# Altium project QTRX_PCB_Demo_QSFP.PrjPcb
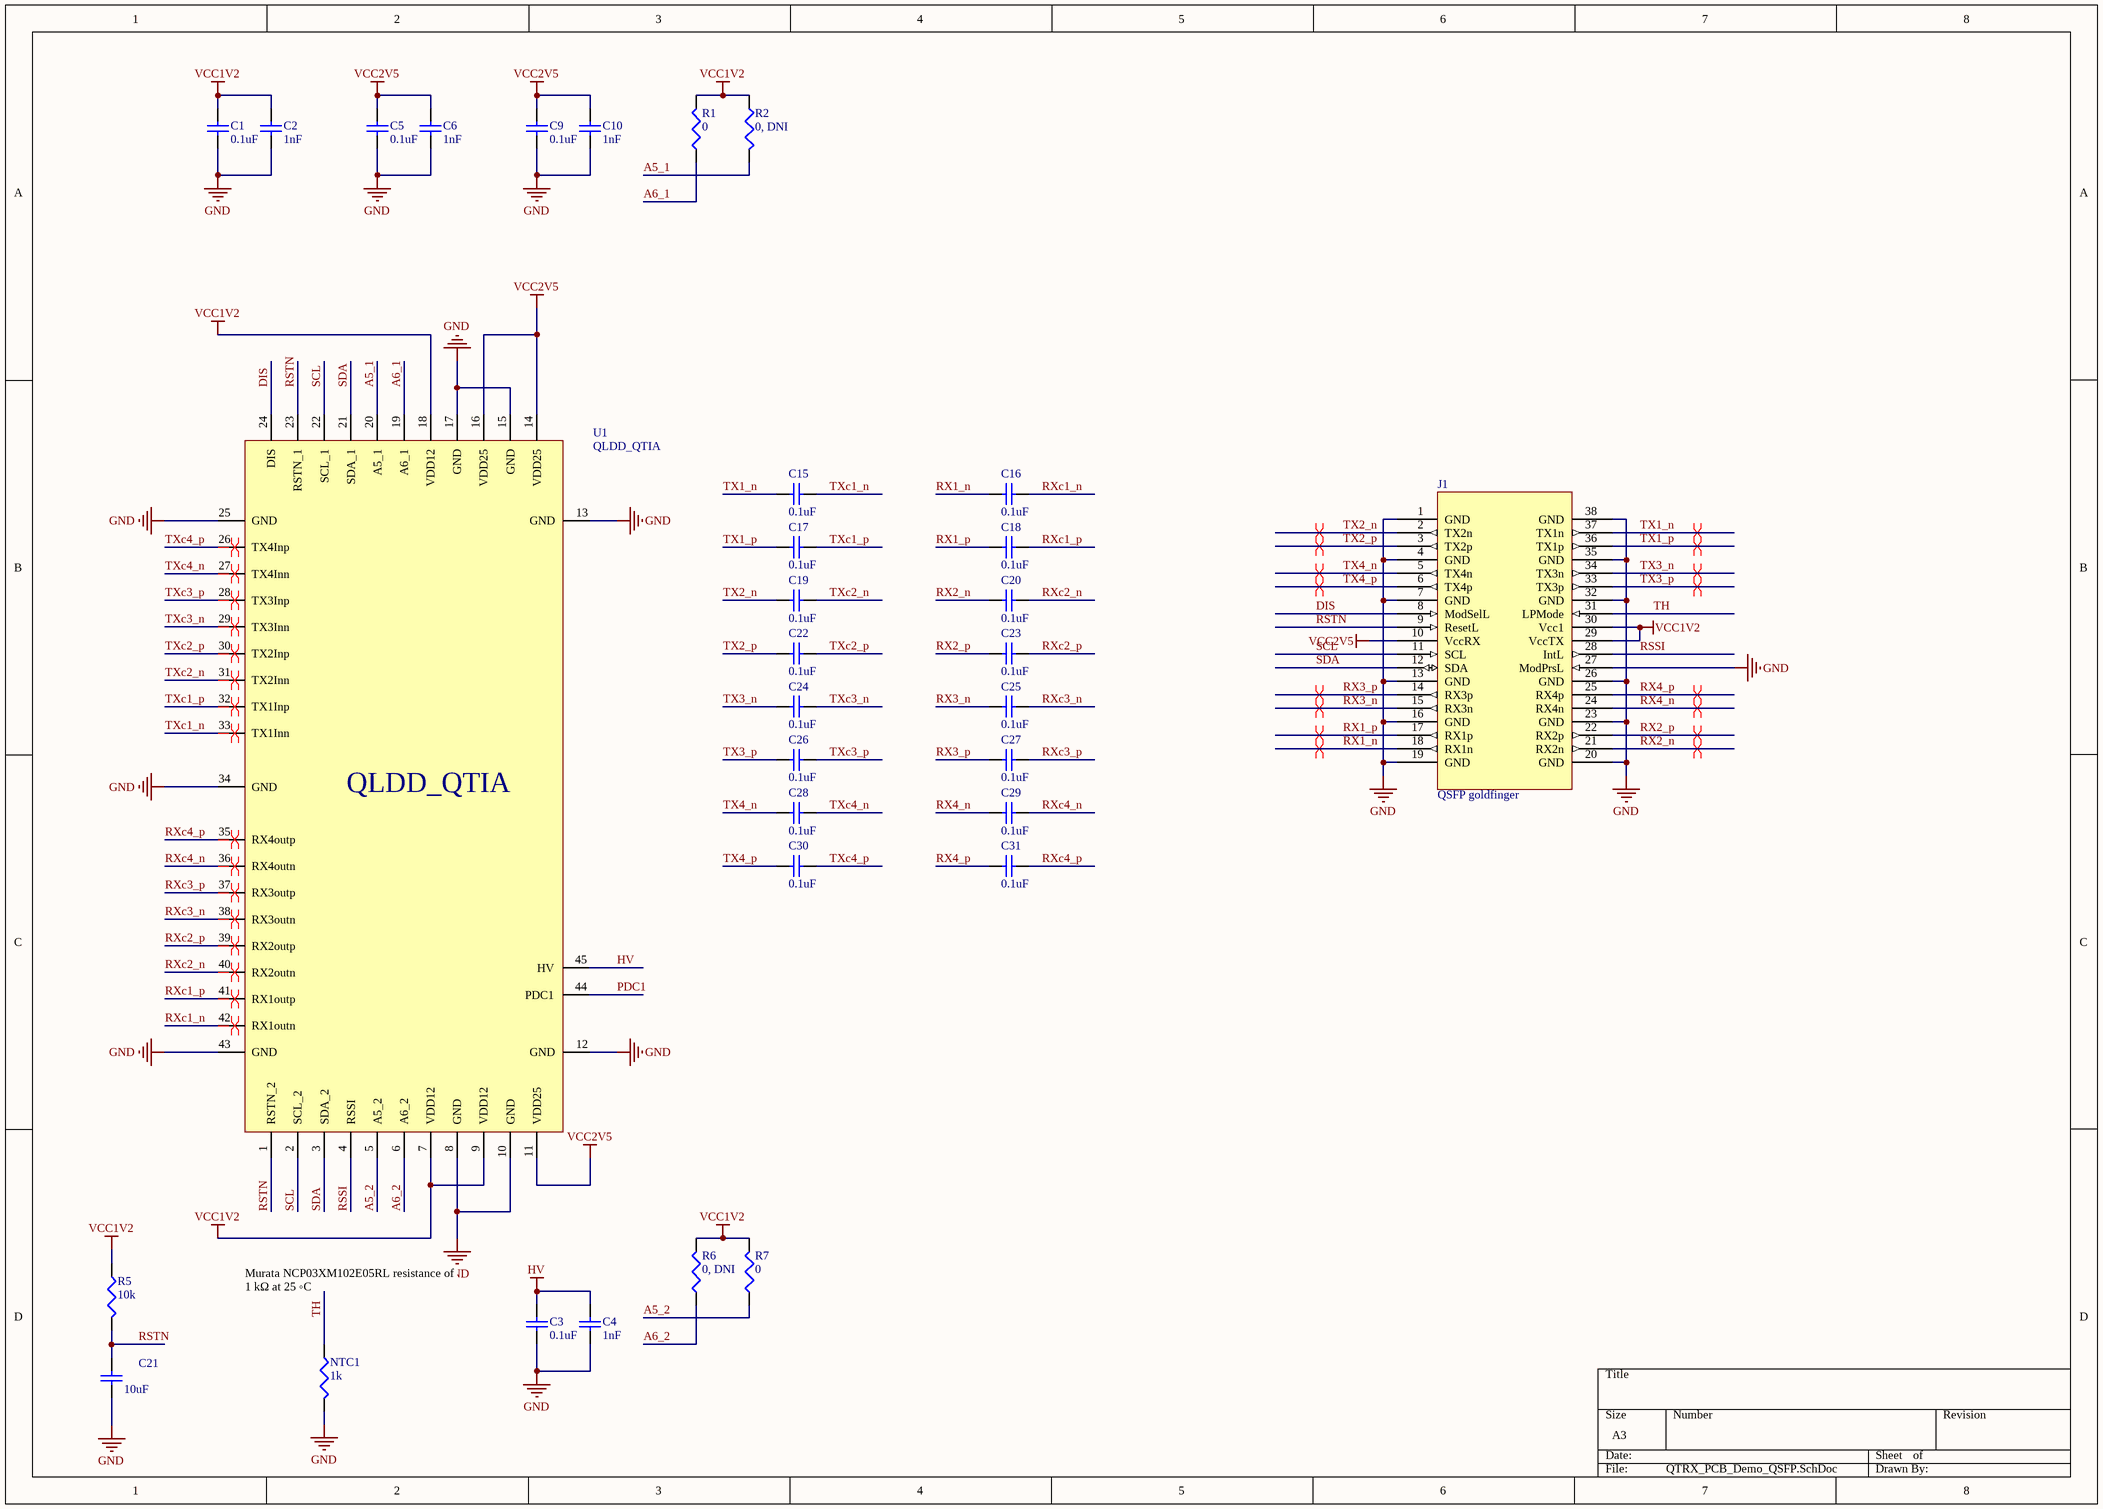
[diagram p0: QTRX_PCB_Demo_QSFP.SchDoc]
1 sheet, 33 parts. Net scope: global (net labels, ports and power ports of the same name join across sheets).
Board file: QTRX_PCB_Demo_QSFP.PcbDoc

## Sheet QTRX_PCB_Demo_QSFP.SchDoc
size A3

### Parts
C1  value 0.1uF  [0402-eagle]  (hidden comment: Cap 0.1uF)
C2  value 1nF  [0402-eagle]  (hidden comment: Cap 1nF)
C3  value 0.1uF  [0402-eagle]  (hidden comment: Cap 0.1uF)
C4  value 1nF  [0402-eagle]  (hidden comment: Cap 1nF)
C5  value 0.1uF  [0402-eagle]  (hidden comment: Cap 0.1uF)
C6  value 1nF  [0402-eagle]  (hidden comment: Cap 1nF)
C9  value 0.1uF  [0402-eagle]  (hidden comment: Cap 0.1uF)
C10  value 1nF  [0402-eagle]  (hidden comment: Cap 1nF)
C15  value 0.1uF  [0201-eagle]  (hidden comment: Cap 0.1uF)
C16  value 0.1uF  [0201-eagle]  (hidden comment: Cap 0.1uF)
C17  value 0.1uF  [0201-eagle]  (hidden comment: Cap 0.1uF)
C18  value 0.1uF  [0201-eagle]  (hidden comment: Cap 0.1uF)
C19  value 0.1uF  [0201-eagle]  (hidden comment: Cap 0.1uF)
C20  value 0.1uF  [0201-eagle]  (hidden comment: Cap 0.1uF)
C21  value 10uF  [0402-eagle]  (hidden comment: Cap semi 10 uF)
C22  value 0.1uF  [0201-eagle]  (hidden comment: Cap 0.1uF)
C23  value 0.1uF  [0201-eagle]  (hidden comment: Cap 0.1uF)
C24  value 0.1uF  [0201-eagle]  (hidden comment: Cap 0.1uF)
C25  value 0.1uF  [0201-eagle]  (hidden comment: Cap 0.1uF)
C26  value 0.1uF  [0201-eagle]  (hidden comment: Cap 0.1uF)
C27  value 0.1uF  [0201-eagle]  (hidden comment: Cap 0.1uF)
C28  value 0.1uF  [0201-eagle]  (hidden comment: Cap 0.1uF)
C29  value 0.1uF  [0201-eagle]  (hidden comment: Cap 0.1uF)
C30  value 0.1uF  [0201-eagle]  (hidden comment: Cap 0.1uF)
C31  value 0.1uF  [0201-eagle]  (hidden comment: Cap 0.1uF)
J1  QSFP goldfinger  [QSFP GOLDFINGER]
NTC1  value 1k  [0201-res]  (hidden comment: 1k Thermistor)
R1  value 0  [0402-eagle_Res]  (hidden comment: Res 0 Ohm)
R2  value 0, DNI  [0402-eagle_Res]  (hidden comment: Res 0 Ohm,DNI)
R5  value 10k  [0402-eagle_Res]  (hidden comment: Res 10k)
R6  value 0, DNI  [0402-eagle_Res]  (hidden comment: Res 0 Ohm,DNI)
R7  value 0  [0402-eagle_Res]  (hidden comment: Res 0 Ohm)
U1  QLDD_QTIA  [QTRX_2p75Lens_v2]

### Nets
GND: C1.1 C2.1 C3.1 C4.1 C5.1 C6.1 C9.1 C10.1 C21.2 J1.1(GND) J1.4(GND) J1.7(GND) J1.13(GND) J1.16(GND) J1.19(GND) J1.20(GND) J1.23(GND) J1.26(GND) J1.27(ModPrsL) J1.32(GND) J1.35(GND) J1.38(GND) NTC1.2 U1.8(GND) U1.10(GND) U1.12(GND) U1.13(GND) U1.15(GND) U1.17(GND) U1.25(GND) U1.34(GND) U1.43(GND)
HV: C3.2 C4.2 U1.45(HV)
VCC1V2: C1.2 C2.2 J1.29(VccTX) J1.30(Vcc1) R1.2 R2.1 R5.1 R6.2 R7.2 U1.7(VDD12) U1.9(VDD12) U1.18(VDD12)
VCC2V5: C5.2 C6.2 C9.2 C10.2 J1.10(VccRX) U1.11(VDD25) U1.14(VDD25) U1.16(VDD25)
A5_1: R2.2 U1.20(A5_1)
A5_2: R7.1 U1.5(A5_2)
A6_1: R1.1 U1.19(A6_1)
A6_2: R6.1 U1.6(A6_2)
DIS: J1.8(ModSelL) U1.24(DIS)
PDC1: U1.44(PDC1)
RSSI: J1.28(IntL) U1.4(RSSI)
RSTN: C21.1 J1.9(ResetL) R5.2 U1.1(RSTN_2) U1.23(RSTN_1)
RX1_n: C16.1 J1.18(RX1n)
RX1_p: C18.1 J1.17(RX1p)
RX2_n: C20.1 J1.21(RX2n)
RX2_p: C23.1 J1.22(RX2p)
RX3_n: C25.1 J1.15(RX3n)
RX3_p: C27.1 J1.14(RX3p)
RX4_n: C29.1 J1.24(RX4n)
RX4_p: C31.1 J1.25(RX4p)
RXc1_n: C16.2 U1.42(RX1outn)
RXc1_p: C18.2 U1.41(RX1outp)
RXc2_n: C20.2 U1.40(RX2outn)
RXc2_p: C23.2 U1.39(RX2outp)
RXc3_n: C25.2 U1.38(RX3outn)
RXc3_p: C27.2 U1.37(RX3outp)
RXc4_n: C29.2 U1.36(RX4outn)
RXc4_p: C31.2 U1.35(RX4outp)
SCL: J1.11(SCL) U1.2(SCL_2) U1.22(SCL_1)
SDA: J1.12(SDA) U1.3(SDA_2) U1.21(SDA_1)
TH: J1.31(LPMode) NTC1.1
TX1_n: C15.1 J1.37(TX1n)
TX1_p: C17.1 J1.36(TX1p)
TX2_n: C19.1 J1.2(TX2n)
TX2_p: C22.1 J1.3(TX2p)
TX3_n: C24.1 J1.34(TX3n)
TX3_p: C26.1 J1.33(TX3p)
TX4_n: C28.1 J1.5(TX4n)
TX4_p: C30.1 J1.6(TX4p)
TXc1_n: C15.2 U1.33(TX1Inn)
TXc1_p: C17.2 U1.32(TX1Inp)
TXc2_n: C19.2 U1.31(TX2Inn)
TXc2_p: C22.2 U1.30(TX2Inp)
TXc3_n: C24.2 U1.29(TX3Inn)
TXc3_p: C26.2 U1.28(TX3Inp)
TXc4_n: C28.2 U1.27(TX4Inn)
TXc4_p: C30.2 U1.26(TX4Inp)

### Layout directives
differential pair: RX1_n, RX1_p, RX2_n, RX2_p, RX3_n, RX3_p, RX4_n, RX4_p, RXc1_n, RXc1_p, RXc2_n, RXc2_p, RXc3_n, RXc3_p, RXc4_n, RXc4_p, TX1_n, TX1_p, TX2_n, TX2_p, TX3_n, TX3_p, TX4_n, TX4_p, TXc1_n, TXc1_p, TXc2_n, TXc2_p, TXc3_n, TXc3_p, TXc4_n, TXc4_p

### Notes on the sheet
- Murata NCP03XM102E05RL resistance of 1 kΩ at 25 ◦C

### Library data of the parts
C1-C6 C9 C10 C15-C31 = Cap: Capacitor
NTC1 = Res3: Murata NCP03XM102E05RL
R1 R7 = Res3_2: Resistor
R2 R6 = Res3_3: Resistor
R5 = Res3: Resistor

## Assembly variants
I2C_Config: not fitted R2 R3 R6 R9 R10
